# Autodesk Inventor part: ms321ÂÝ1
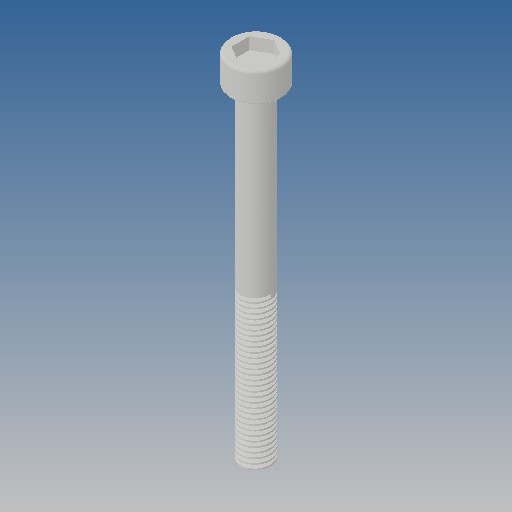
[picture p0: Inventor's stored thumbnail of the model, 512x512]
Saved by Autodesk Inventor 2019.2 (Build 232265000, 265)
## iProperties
Created: 2013-07
Part Number: ms321ÂÝ1
Material: Ogólny
Document SubType Name: Modeling
Designer: CADENGINEERING4
Density: 1 g/cm^3
Appearance: Domyślna
Author: CADENGINEERING4
Revision Number: ÈÎºÎ
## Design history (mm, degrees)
feature "ÇÐ³ý-É¨Ãè1"
node "Bryła1"
